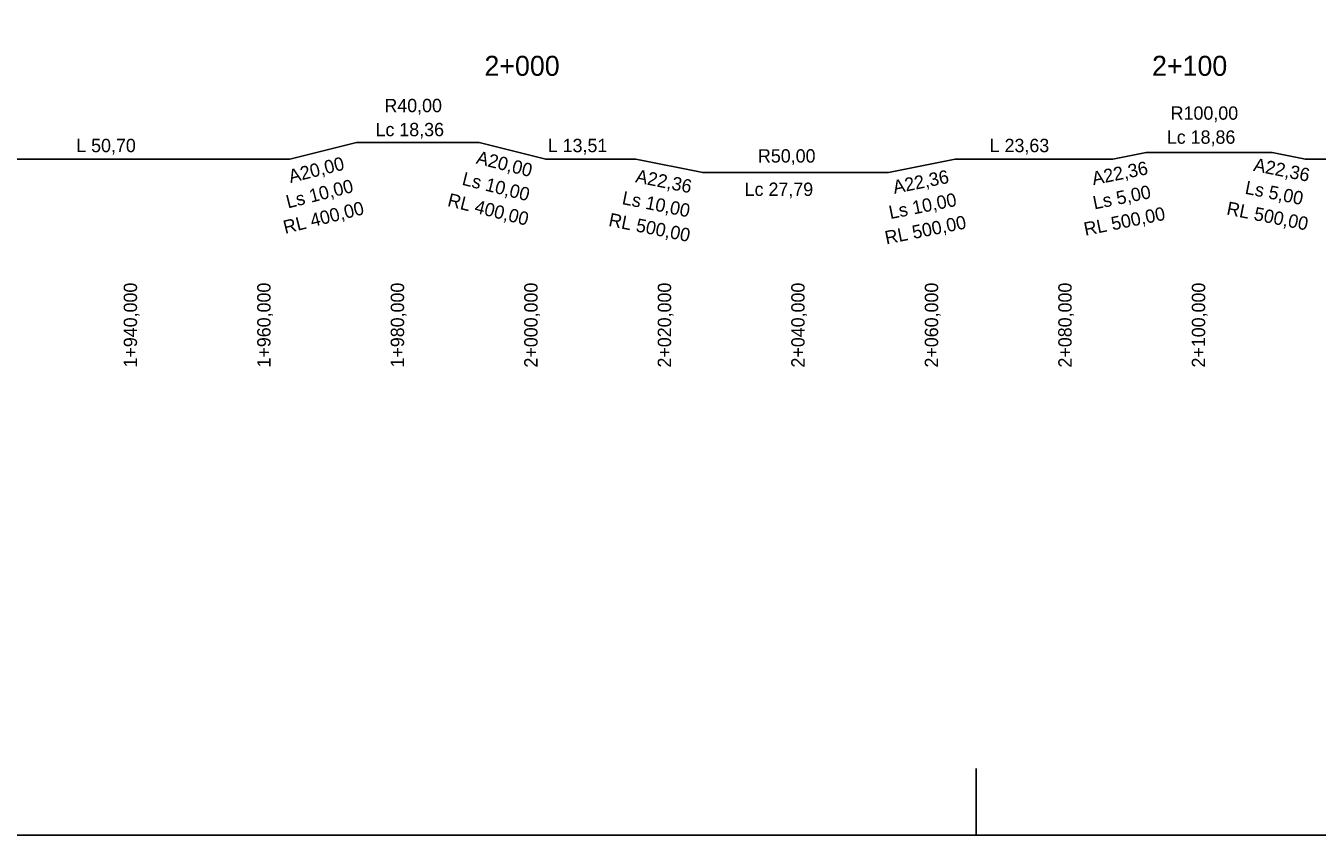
# Model space of a CAD drawing. Extents: x -632716 to -629545, y -1094726 to -1088285.
# Drawn here: x -630527.6 to -630334.2, y -1090378.9 to -1090257.6 of the extents above; entities that cross this region are included whole.
import ezdxf

# ---------------------------------------------------------------- set-up
doc = ezdxf.new("R2010")
doc.units = 0
for name, color, linetype in [('formát', 7, 'Continuous'), ('REZ_POPIS', 7, 'Continuous'), ('REZ_TABULKA', 7, 'Continuous')]:
    doc.layers.add(name, color=color, linetype=linetype)

msp = doc.modelspace()

# ---------------------------------------------------------------- linework, layer by layer
at = {"layer": 'formát'}
msp.add_line((-630385.24, -1090378.9), (-630385.24, -1090368.9), dxfattribs=at)
msp.add_lwpolyline([(-632546.83, -1090378.9), (-629545.24, -1090378.9), (-629545.24, -1089784.9), (-632546.83, -1089784.9)], close=True, dxfattribs=at)
at = {"layer": 'REZ_TABULKA'}
msp.add_lwpolyline([(-630538.78, -1090277.62), (-630488.08, -1090277.62), (-630488.08, -1090277.62), (-630478.08, -1090275.12), (-630478.08, -1090275.12), (-630459.72, -1090275.12), (-630459.72, -1090275.12), (-630449.72, -1090277.62), (-630449.72, -1090277.62), (-630436.21, -1090277.62), (-630436.21, -1090277.62), (-630426.21, -1090279.62), (-630426.21, -1090279.62), (-630398.41, -1090279.62), (-630398.41, -1090279.62), (-630388.41, -1090277.62), (-630388.41, -1090277.62), (-630364.79, -1090277.62), (-630364.79, -1090277.62), (-630359.79, -1090276.62), (-630359.79, -1090276.62), (-630340.93, -1090276.62), (-630340.93, -1090276.62), (-630335.93, -1090277.62), (-630335.93, -1090277.62), (-630315.26, -1090277.62)], dxfattribs=at)

# ---------------------------------------------------------------- texts
at = {"layer": 'REZ_POPIS'}
for s, p in [('2+000', (-630458.91, -1090265.12)), ('2+100', (-630358.91, -1090265.12))]:
    msp.add_text(s, height=3, dxfattribs=at).set_placement(p)
at = {"layer": 'REZ_TABULKA'}
for s, p in [('R40,00', (-630473.9, -1090270.57)), ('R100,00', (-630356.12, -1090271.7)), ('Lc 18,36', (-630475.23, -1090274.17)), ('Lc 18,86', (-630356.69, -1090275.3)), ('L 50,70', (-630520.06, -1090276.56)), ('L 13,51', (-630449.43, -1090276.56)), ('L 23,63', (-630383.23, -1090276.56)), ('R50,00', (-630417.94, -1090278.12)), ('Lc 27,79', (-630419.93, -1090283.12))]:
    msp.add_text(s, height=2, dxfattribs=at).set_placement(p)
for s, rotation, p in [('A20,00', 14.0362, (-630487.97, -1090281.2)), ('A20,00', 345.9638, (-630460.27, -1090278.25)), ('A22,36', 348.6901, (-630436.39, -1090281.06)), ('A22,36', 11.3099, (-630397.51, -1090282.81)), ('A22,36', 11.3099, (-630367.7, -1090281.51)), ('A22,36', 348.6901, (-630343.82, -1090279.35)), ('Ls 10,00', 14.0362, (-630488.35, -1090285)), ('Ls 10,00', 345.9638, (-630462.39, -1090281.43)), ('Ls 5,00', 348.6901, (-630345.09, -1090282.77)), ('RL 400,00', 345.9638, (-630464.56, -1090284.6)), ('Ls 10,00', 348.6901, (-630438.41, -1090284.33)), ('Ls 10,00', 11.3099, (-630398.11, -1090286.6)), ('Ls 5,00', 11.3099, (-630367.55, -1090285.15)), ('RL 400,00', 14.0362, (-630488.77, -1090288.82)), ('RL 500,00', 11.3099, (-630368.9, -1090289.1)), ('RL 500,00', 348.6901, (-630347.85, -1090285.89)), ('RL 500,00', 348.6901, (-630440.42, -1090287.6)), ('RL 500,00', 11.3099, (-630398.71, -1090290.39)), ('1+940,000', 90, (-630510.95, -1090308.83)), ('1+960,000', 90, (-630490.95, -1090308.83)), ('1+980,000', 90, (-630470.95, -1090308.83)), ('2+000,000', 90, (-630450.95, -1090308.83)), ('2+020,000', 90, (-630430.95, -1090308.83)), ('2+040,000', 90, (-630410.95, -1090308.83)), ('2+060,000', 90, (-630390.95, -1090308.83)), ('2+080,000', 90, (-630370.95, -1090308.83)), ('2+100,000', 90, (-630350.95, -1090308.83))]:
    msp.add_text(s, height=2, rotation=rotation, dxfattribs=at).set_placement(p)

doc.saveas('drawing.dxf')
